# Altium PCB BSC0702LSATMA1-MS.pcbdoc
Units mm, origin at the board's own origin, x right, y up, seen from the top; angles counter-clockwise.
Board outline 18.5 x 19.71 mm, 2 copper layers (Top Layer, Bottom Layer), stack 0 mm thick; 1 components, 0 nets, 9 pads, 0 vias.
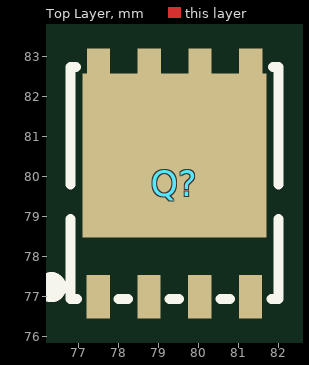
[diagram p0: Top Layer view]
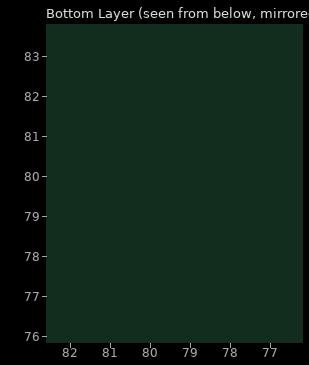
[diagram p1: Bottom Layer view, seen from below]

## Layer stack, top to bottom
Top Layer: signal copper (thickness not stored)
Bottom Layer: signal copper (thickness not stored)

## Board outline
88.35,69.85 69.85,69.85 69.85,89.565 88.35,89.565

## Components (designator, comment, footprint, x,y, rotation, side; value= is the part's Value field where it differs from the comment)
Q? "BSC0702LSATMA1-MS" PDFN-8_L4.9-W5.8-P1.27-LS6.1-BL 79.402,79.84 r0 top

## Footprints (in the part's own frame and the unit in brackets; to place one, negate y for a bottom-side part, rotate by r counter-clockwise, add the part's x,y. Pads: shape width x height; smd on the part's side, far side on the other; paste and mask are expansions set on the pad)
PDFN-8_L4.9-W5.8-P1.27-LS6.1-BL [mm]
  rect 0.58x1.079 smd paste-100 mask+0.05: 1(-1.907,-2.835) 2(-0.637,-2.835) 3(0.633,-2.835) 4(1.903,-2.835)
  rect 0.58x1.08 smd paste-100 mask+0.05: 5(1.907,2.835) 6(0.638,2.835) 7(-0.632,2.835) 8(-1.902,2.835)
  rect 4.6x4.1 smd paste-100 mask+0.05: 9(-0.002,0.695)
  silkscreen extent -3.2,-2.89 2.6,2.9

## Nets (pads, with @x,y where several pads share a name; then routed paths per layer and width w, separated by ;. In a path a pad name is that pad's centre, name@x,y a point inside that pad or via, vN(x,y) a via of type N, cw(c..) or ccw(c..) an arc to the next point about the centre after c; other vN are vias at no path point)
pads on no net: Q?.1 Q?.2 Q?.3 Q?.4 Q?.5 Q?.6 Q?.7 Q?.8 Q?.9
